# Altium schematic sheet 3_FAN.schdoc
size 307 x 218 mm; Symbol: Drawing-Symbol_A4; Device: Drawing-Symbol_A4; @Project Name: Bed Temp Regulation; @Page Count: 4; @Update Date: 2026-02-17; @Create Date: 2026-02-16; @Schematic Name: Schematic Main; @Page No: 3; @Page Name: FAN; Company: EasyEDA.com; Version: V1.0; Page Size: A4; @Create Time: 11:31:32; @Update Time: 15:18:19; Width: 1170; Height: 825; Region Start: 1; X Region Count: 6; Y Region Count: 4; Blade Width: 10; Title Block Position: 3; @Board Name: Main Board
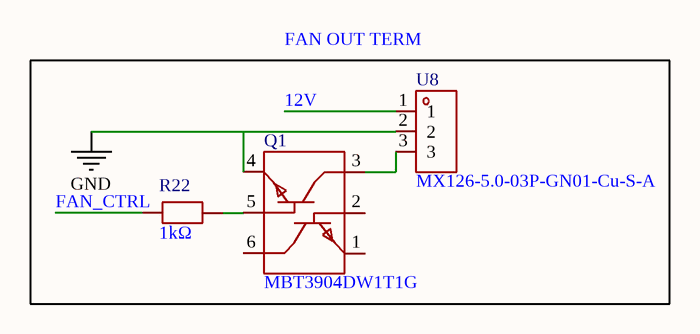
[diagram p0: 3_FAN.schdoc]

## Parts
Q1  MBT3904DW1T1G  [SOT-363_L2.0-W1.3-P0.65-LS2.1-TL]
R22  1kΩ  [R0805]
U8  MX126-5.0-03P-GN01-Cu-S-A  [CONN-TH_3P-P5.00_MAX_MX126-5.0-GN01-03P-CU-S-A]

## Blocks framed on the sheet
FAN OUT TERM: Q1 R22 U8

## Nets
GND: Q1.4 U8.2
12V: U8.1
FAN_CTRL: R22.1
NetQ1_3: Q1.3 U8.3
NetQ1_5: Q1.5 R22.2

Not connected (* = marked no-connect by the designer): Q1 1 2 6

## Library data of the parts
Q1 = MBT3904DW1T1G: Manufacturer: onsemi(安森美); Add into BOM: yes; type: NPN; Current - Collector(Ic): 200mA; Collector - Emitter Voltage VCEO: 40V; Pd - Power Dissipation: 150mW; DC Current Gain: 100@10mA,1.0V; Transition frequency(fT): 300MHz; Current - Collector Cutoff: 50nA; Vce Saturation(VCE(sat)): 300mV@50mA,5mA; Emitter-Base Voltage(Vebo): 6V
R22 = FRC0805J102 TS: Manufacturer: FOJAN(富捷); Add into BOM: yes; Tolerance: ±5%; Power(Watts): 125mW; Voltage-Supply(Max): 150V; Temperature Coefficient: ±100ppm/℃
U8 = MX126-5.0-03P-GN01-Cu-S-A: Manufacturer: MAX(迈旭); Symbol: MX126-5.0-GN01-03P-CU-S-A; Add into BOM: yes; Number of Positions or Pins: 1x3P; Pitch: 5mm; Number of PINs Per Row: 3; Screw Specification: M2.5; Current Rating: 10A; Voltage Rating (Max): 300V; Wire Gauge - AWG: 14~26; Wire Gauge - mm2: 2.5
